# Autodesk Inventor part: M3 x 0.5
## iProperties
IsCustomPart: 0
Created: 2015-10
Part Number: M3 x 0.5
Material: 강, 연강
Description: 6각머리 태핑 나사
Document SubType Name: Modeling
Standard: KS B 1003
Designer: mdu
Standards Organization: KS
Language: ko-KR
Size Designation: M 3 x 12
Categories: <MemberInstance><Categories><Category DisplayName="조임쇠" InternalName="e4da775c-781d-43d5-af7c-5136215cf5a6" Mnemonic="FSTN"><Category DisplayName="볼트" InternalN
Density: 1 g/cm^3
Author: mdu
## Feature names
1. Fillet2
